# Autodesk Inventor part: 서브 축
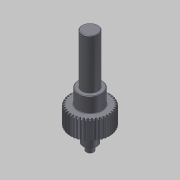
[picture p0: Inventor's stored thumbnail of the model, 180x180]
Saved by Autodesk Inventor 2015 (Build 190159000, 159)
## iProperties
Created: 2016-02
Part Number: 서브 축
Material: 강철, 연강
Document SubType Name: Modeling
Designer: mdu
Categories: <?xml version="1.0" encoding="UTF-16"?> <MemberInstance><Categories><FamilyTemplate><FamilyTemplateParameter ValueType="xs:double" Id="1" ObjectReferenceKey="da
Density: 7.86 g/cm^3
Appearance: Steel
CustomPartVersion: 1
Author: mdu
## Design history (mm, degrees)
sketch "Sketch1"
  geometry: C1 r 21 at (0, 0)
  constraints: 1 centre point
  dimensions: "d0" = 42 diameter of C1 (= da_da)
extrude "Extrusion1" new body sketch "Sketch1" distance "d1" = 20 (= da_b); taper "d2" = 0 deg
workplane "Work Plane2"
feature "피치 지름" dims "d4" = 10, "d5" = 0
workplane "Work Plane8"
workplane "Work Plane9"
chamfer "모따기1" distance "d49" = 1; stored, may be unused: second distance "d50" = 2, angle "d51" = 45 deg
sketch "스케치3"
  geometry: C1 r 12.5 at (0, 0); 1 further point
  constraints: 1 centre point, 1 coincident
  dimensions: "d52" = 25 diameter of C1
extrude "돌출2" join sketch "스케치3" distance "d53" = 16; taper "d54" = 0 deg
sketch "스케치4"
  geometry: C1 r 8.5 at (0, 0); 1 further point
  constraints: 1 centre point, 1 coincident
  dimensions: "d55" = 17 diameter of C1
extrude "돌출3" join sketch "스케치4" distance "d56" = 53; taper "d57" = 0 deg
sketch "스케치5"
  geometry: C1 r 7.5 at (0, 0); 1 further point
  constraints: 1 centre point, 1 coincident
  dimensions: "d62" = 15 diameter of C1
extrude "돌출4" join sketch "스케치5" distance "d63" = 16; taper "d64" = 0 deg
sketch "스케치6"
  geometry: C1 r 4 at (0, 0); 1 further point
  constraints: 1 centre point, 1 coincident
  dimensions: "d65" = 8 diameter of C1
extrude "돌출5" join sketch "스케치6" distance "d66" = 7; taper "d67" = 0 deg
chamfer "모따기2" distance "d58" = 0.5; stored, may be unused: second distance "d59" = 2, angle "d60" = 45 deg
fillet "모깎기1" dims "d61" = 0.5
feature "스퍼 기어" dims "da_b" = 20, "da_d" = 40, "da_aw" = 31, "da_da" = 42, "da_df" = 37.5, "da_dw" = 40, angle "da_beta" = 0 deg, "da_lefttooth" = 0, "da_righttooth" = 0
body "Solid1"
sketch "Sketch2"
  geometry: C1 r 21 at (0, 0) reference; C2 r 20 at (0, 0)
  constraints: 1 centre point, 1 coincident
  dimensions: "d3" = 40 diameter of C2 (= da_dw)
body "Srf1"
other parameters: "d16" = 31 (= da_aw), "d17" = 0, "d34" = 4.5 deg (computed from da_z), "d39" = 0, "d41" = 0, "d43" = 31 (= da_aw), "d46" = 31 (= da_aw), "d47" = 0, "d48" = 0
